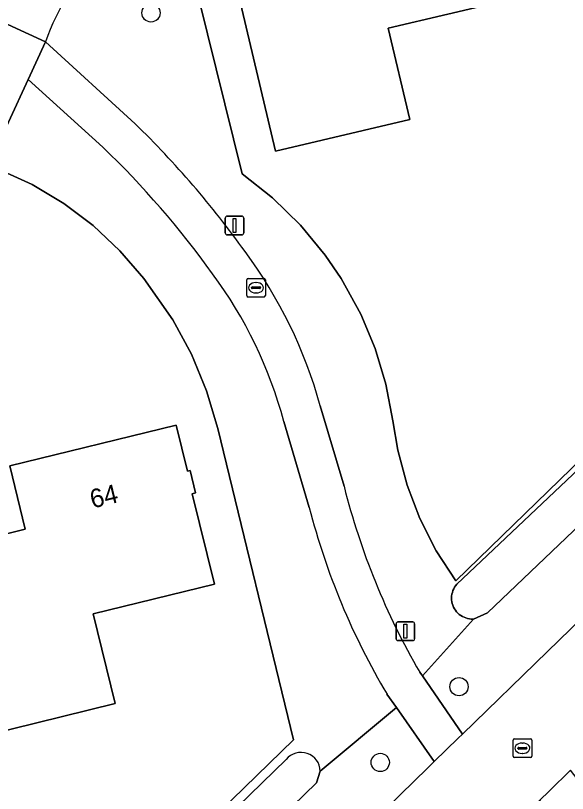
# Model space of a CAD drawing. Extents: x 157648 to 158502, y 379212 to 380938.
# Drawn here: x 158248.91 to 158278.51, y 380472.37 to 380514.11 of the extents above; entities that cross this region are included whole.
import ezdxf

# ---------------------------------------------------------------- set-up
doc = ezdxf.new("R2010")
doc.units = 0
for name, color, linetype in [('IMGEO_Berm_groen', 7, 'Continuous'), ('IMGEO_Boom', 7, 'Continuous'), ('IMGEO_Erf', 7, 'Continuous'), ('IMGEO_Groenvoorziening', 7, 'Continuous'), ('IMGEO_Lichtmast', 7, 'Continuous'), ('IMGEO_Pand', 7, 'Continuous'), ('IMGEO_Pand_nummerreeks', 7, 'Continuous'), ('IMGEO_Rijbaan_lokaal_gesloten', 7, 'Continuous'), ('IMGEO_Rioolput', 7, 'Continuous'), ('IMGEO_Voetpad_open', 7, 'Continuous'), ('IMGEO_Waterloop', 7, 'Continuous')]:
    doc.layers.add(name, color=color, linetype=linetype)

msp = doc.modelspace()

# ---------------------------------------------------------------- linework, layer by layer
at = {"layer": 'IMGEO_Berm_groen'}
msp.add_lwpolyline([(158250.925, 380454.131), (158271.031, 380473.749), (158271.369, 380474.079), (158269.334, 380476.98), (158265.254, 380473.57), (158265.055, 380472.934), (158206.97, 380416.487), (158206.469, 380416.402), (158201.9, 380412.048), (158203.076, 380407.926)], close=True, dxfattribs=at)
at = {"layer": 'IMGEO_Boom'}
for centre in [(158256.174, 380514.25), (158272.696, 380478.099), (158268.47, 380474.034)]:
    msp.add_circle(centre, 0.489, dxfattribs=at)
at = {"layer": 'IMGEO_Erf'}
for points in [[(158319.496, 380558.936), (158263.701, 380524.634), (158257.585, 380520.788), (158257.469, 380520.719), (158257.353, 380520.65), (158261.062, 380505.621), (158262.697, 380504.321), (158264.187, 380502.857), (158265.516, 380501.245), (158266.367, 380500), (158267.425, 380498.089), (158268.197, 380496.241), (158268.772, 380494.324), (158269.143, 380492.356), (158269.406, 380490.783), (158269.906, 380488.917), (158270.597, 380487.114), (158271.474, 380485.392), (158272.525, 380483.772), (158289.215, 380500), (158329.422, 380539.101), (158325.742, 380554.195), (158320.483, 380559.775)], [(158275.292, 380514.936), (158268.901, 380513.427), (158270.056, 380508.533), (158262.853, 380506.832), (158260.494, 380516.825)], [(158259.752, 380491.953), (158259.158, 380493.979), (158258.356, 380495.931), (158257.354, 380497.789), (158255.796, 380500), (158254.505, 380501.492), (158253.066, 380502.84), (158251.493, 380504.031), (158249.805, 380505.05), (158247.453, 380506.107), (158245.11, 380501.089), (158241.856, 380493.971)], [(158233.427, 380472.19), (158232.637, 380475.402), (158237.416, 380476.576), (158236.587, 380479.949), (158245.461, 380482.13), (158244.664, 380485.374), (158249.435, 380486.546), (158248.601, 380489.942), (158257.519, 380492.133), (158258.127, 380489.655), (158258.274, 380489.691), (158258.568, 380488.496), (158258.391, 380488.452), (158259.581, 380483.607), (158253.072, 380482.008), (158254.256, 380477.189), (158247.21, 380475.457), (158247.738, 380473.308), (158247.426, 380473.231), (158247.32, 380473.66), (158240.966, 380472.099)], [(158232.056, 380481.111), (158195.106, 380450.632), (158202.56, 380420.525), (158204.989, 380417.99), (158263.809, 380475.249), (158259.752, 380491.953)]]:
    msp.add_lwpolyline(points, dxfattribs=at)
at = {"layer": 'IMGEO_Groenvoorziening'}
for points in [[(158334.137, 380543.912), (158329.422, 380539.101), (158289.215, 380500), (158272.525, 380483.772), (158271.474, 380485.392), (158270.597, 380487.114), (158269.906, 380488.917), (158269.406, 380490.783), (158269.143, 380492.356), (158268.772, 380494.324), (158268.197, 380496.241), (158267.425, 380498.089), (158266.367, 380500), (158265.516, 380501.245), (158264.187, 380502.857), (158262.697, 380504.321), (158261.062, 380505.621), (158257.353, 380520.65)], [(158250.517, 380512.693), (158255.325, 380508.305)], [(158253.591, 380507.049), (158249.589, 380510.681), (158247.453, 380506.107), (158249.805, 380505.05), (158251.493, 380504.031), (158253.066, 380502.84), (158254.505, 380501.492), (158255.796, 380500), (158257.354, 380497.789), (158258.356, 380495.931), (158259.158, 380493.979), (158259.752, 380491.953), (158263.809, 380475.249), (158204.989, 380417.99), (158205.522, 380417.551)], [(158270.591, 380478.878), (158270.73, 380478.676), (158273.465, 380481.728), (158273.452, 380481.728), (158273.351, 380481.729), (158273.251, 380481.739), (158273.153, 380481.759), (158273.056, 380481.787), (158272.963, 380481.823), (158272.873, 380481.868), (158272.788, 380481.92), (158272.707, 380481.98), (158272.632, 380482.047), (158272.564, 380482.121), (158272.502, 380482.2), (158272.448, 380482.284), (158272.401, 380482.373), (158272.363, 380482.466), (158272.332, 380482.562), (158272.311, 380482.66), (158272.299, 380482.76), (158272.295, 380482.86), (158272.3, 380482.96), (158272.315, 380483.06), (158272.338, 380483.157), (158272.37, 380483.252), (158272.41, 380483.344), (158272.458, 380483.433), (158272.514, 380483.516), (158272.577, 380483.594), (158289.923, 380500)], [(158265.256, 380493.17), (158266.53, 380488.852)], [(158264.661, 380487.712), (158263.298, 380492.332)], [(158265.254, 380473.57), (158269.334, 380476.98), (158268.832, 380477.696)], [(158205.787, 380418.134), (158263.422, 380474.193)]]:
    msp.add_lwpolyline(points, dxfattribs=at)
msp.add_lwpolyline([(158332.358, 380537.527), (158293.02, 380500), (158274.224, 380482.069), (158273.465, 380481.728), (158270.73, 380478.676), (158272.883, 380475.555), (158277.441, 380479.984), (158298.039, 380500), (158339.285, 380540.082), (158336.691, 380542), (158332.462, 380538.012)], close=True, dxfattribs=at)
for centre, radius, start, end in [((158263.377, 380508.142), 13.641, 136.3346, 160.5134), ((158219.142, 380471.243), 51.796, 35.6688, 45.6876), ((158219.256, 380471.391), 49.501, 35.6629, 46.083), ((158240.763, 380486.348), 25.425, 15.5636, 36.4254), ((158240.611, 380486.26), 23.485, 14.9846, 36.5662), ((158303.644, 380498.15), 38.261, 194.064, 210.2442), ((158301.93, 380497.356), 38.496, 194.5074, 210.7096), ((158264.223, 380473.542), 1.032, 1.5405, 140.8968)]:
    msp.add_arc(centre, radius, start, end, dxfattribs=at)
at = {"layer": 'IMGEO_Lichtmast'}
for p, q in [((158260.159, 380502.443), (158260.159, 380503.243)), ((158260.159, 380503.243), (158260.159, 380502.443)), ((158260.259, 380503.343), (158261.049, 380503.343)), ((158261.049, 380503.343), (158260.259, 380503.343)), ((158261.149, 380503.243), (158261.149, 380502.443)), ((158261.149, 380502.443), (158261.149, 380503.243)), ((158261.049, 380502.343), (158260.259, 380502.343)), ((158260.259, 380502.343), (158261.049, 380502.343)), ((158269.322, 380480.671), (158269.322, 380481.471)), ((158269.322, 380481.471), (158269.322, 380480.671)), ((158269.422, 380481.571), (158270.212, 380481.571)), ((158270.212, 380481.571), (158269.422, 380481.571)), ((158270.312, 380481.471), (158270.312, 380480.671)), ((158270.312, 380480.671), (158270.312, 380481.471)), ((158270.212, 380480.571), (158269.422, 380480.571)), ((158269.422, 380480.571), (158270.212, 380480.571))]:
    msp.add_line(p, q, dxfattribs=at)
for points in [[(158260.579, 380503.218), (158260.729, 380503.218), (158260.729, 380502.468), (158260.579, 380502.468), (158260.579, 380503.218)], [(158269.742, 380481.446), (158269.892, 380481.446), (158269.892, 380480.696), (158269.742, 380480.696), (158269.742, 380481.446)]]:
    msp.add_lwpolyline(points, dxfattribs=at)
for centre, start, end in [((158260.259, 380503.243), 90, 180), ((158260.259, 380503.243), 90, 180), ((158261.049, 380503.243), 0, 90), ((158261.049, 380503.243), 360, 90), ((158260.259, 380502.443), 180, 270), ((158260.259, 380502.443), 180, 270), ((158261.049, 380502.443), 270, 0), ((158261.049, 380502.443), 270, 0), ((158269.422, 380481.471), 90, 180), ((158269.422, 380481.471), 90, 180), ((158270.212, 380481.471), 0, 90), ((158270.212, 380481.471), 360, 90), ((158269.422, 380480.671), 180, 270), ((158269.422, 380480.671), 180, 270), ((158270.212, 380480.671), 270, 0), ((158270.212, 380480.671), 270, 0)]:
    msp.add_arc(centre, 0.1, start, end, dxfattribs=at)
at = {"layer": 'IMGEO_Pand'}
for points in [[(158273.263, 380523.53), (158264.531, 380521.468), (158265.356, 380517.973), (158260.494, 380516.825), (158262.853, 380506.832), (158270.056, 380508.533), (158268.901, 380513.427), (158275.292, 380514.936)], [(158258.391, 380488.452), (158258.568, 380488.496), (158258.274, 380489.691), (158258.127, 380489.655), (158257.519, 380492.133), (158248.601, 380489.942), (158249.435, 380486.546), (158244.664, 380485.374), (158245.461, 380482.13), (158247.21, 380475.457), (158254.256, 380477.189), (158253.072, 380482.008), (158259.581, 380483.607)]]:
    msp.add_lwpolyline(points, close=True, dxfattribs=at)
at = {"layer": 'IMGEO_Rijbaan_lokaal_gesloten'}
msp.add_lwpolyline([(158298.039, 380500), (158277.441, 380479.984), (158272.883, 380475.555), (158272.656, 380475.334), (158271.369, 380474.079), (158271.031, 380473.749), (158250.925, 380454.131), (158203.076, 380407.926), (158202.965, 380407.819), (158201.329, 380406.238), (158201.205, 380406.119), (158169.223, 380374.76), (158172.867, 380370.956), (158173.119, 380370.694), (158174.013, 380371.614), (158174.854, 380372.479), (158183.798, 380381.68), (158203.283, 380400.795), (158204.847, 380402.186), (158204.985, 380402.319), (158277.006, 380471.994), (158277.54, 380472.51), (158278.68, 380473.614)], dxfattribs=at)
at = {"layer": 'IMGEO_Rioolput'}
for p, q in [((158261.31, 380499.079), (158261.31, 380499.931)), ((158261.385, 380500.005), (158262.237, 380500.005)), ((158261.798, 380499.785), (158261.823, 380499.785)), ((158262.311, 380499.931), (158262.311, 380499.079)), ((158261.569, 380499.499), (158261.569, 380499.511)), ((158262.007, 380499.462), (158261.609, 380499.462)), ((158261.612, 380499.548), (158262.01, 380499.548)), ((158261.821, 380499.225), (158261.796, 380499.225)), ((158262.053, 380499.511), (158262.053, 380499.499)), ((158262.237, 380499.005), (158261.385, 380499.005)), ((158275.595, 380474.371), (158275.595, 380475.223)), ((158275.67, 380475.297), (158276.522, 380475.297)), ((158276.083, 380475.077), (158276.108, 380475.077)), ((158276.596, 380475.223), (158276.596, 380474.371)), ((158275.854, 380474.791), (158275.854, 380474.803)), ((158276.292, 380474.754), (158275.894, 380474.754)), ((158275.897, 380474.84), (158276.295, 380474.84)), ((158276.338, 380474.803), (158276.338, 380474.791)), ((158276.522, 380474.297), (158275.67, 380474.297)), ((158276.106, 380474.517), (158276.081, 380474.517))]:
    msp.add_line(p, q, dxfattribs=at)
for points in [[(158261.31, 380499.079), (158261.31, 380499.931)], [(158261.385, 380500.005), (158262.237, 380500.005)], [(158262.311, 380499.931), (158262.311, 380499.079)], [(158262.237, 380499.005), (158261.385, 380499.005)], [(158275.595, 380474.371), (158275.595, 380475.223)], [(158275.67, 380475.297), (158276.522, 380475.297)], [(158276.596, 380475.223), (158276.596, 380474.371)], [(158276.522, 380474.297), (158275.67, 380474.297)]]:
    msp.add_lwpolyline(points, dxfattribs=at)
for centre, radius, start, end in [((158261.387, 380499.929), 0.0765, 91.552, 178.448), ((158261.387, 380499.929), 0.0765, 91.552, 178.448), ((158262.235, 380499.929), 0.0765, 1.552, 88.448), ((158262.235, 380499.929), 0.0765, 1.552, 88.448), ((158261.609, 380499.508), 0.0403, 85.8775, 175.7526), ((158261.606, 380499.498), 0.0366, 178.938, 274.7102), ((158262.01, 380499.505), 0.043, 264.8664, 352.4533), ((158262.014, 380499.51), 0.0386, 1.7309, 96.639), ((158261.387, 380499.081), 0.0765, 181.552, 268.448), ((158261.387, 380499.081), 0.0765, 181.552, 268.448), ((158262.235, 380499.081), 0.0765, 271.552, 358.448), ((158262.235, 380499.081), 0.0765, 271.552, 358.448), ((158275.672, 380475.221), 0.0765, 91.552, 178.448), ((158275.672, 380475.221), 0.0765, 91.552, 178.448), ((158276.52, 380475.221), 0.0765, 1.552, 88.448), ((158276.52, 380475.221), 0.0765, 1.552, 88.448), ((158275.894, 380474.8), 0.0403, 85.8775, 175.7526), ((158275.891, 380474.79), 0.0366, 178.938, 274.7102), ((158276.295, 380474.797), 0.043, 264.8664, 352.4533), ((158276.299, 380474.802), 0.0386, 1.7309, 96.639), ((158275.672, 380474.373), 0.0765, 181.552, 268.448), ((158275.672, 380474.373), 0.0765, 181.552, 268.448), ((158276.52, 380474.373), 0.0765, 271.552, 358.448), ((158276.52, 380474.373), 0.0765, 271.552, 358.448)]:
    msp.add_arc(centre, radius, start, end, dxfattribs=at)
for centre, major_axis, ratio, start_param, end_param in [((158261.797, 380499.505), (-0.387, 0.002), 0.722429, 4.712389, 7.853982), ((158261.822, 380499.505), (-0.39, 0.002), 0.717154, 1.570796, 4.712389), ((158276.082, 380474.797), (-0.387, 0.002), 0.722429, 4.712389, 7.853982), ((158276.107, 380474.797), (-0.39, 0.002), 0.717154, 1.570796, 4.712389)]:
    msp.add_ellipse(centre, major_axis=major_axis, ratio=ratio, start_param=start_param, end_param=end_param, dxfattribs=at)
at = {"layer": 'IMGEO_Voetpad_open'}
for points in [[(158248.235, 380515.431), (158247.594, 380514.038), (158250.517, 380512.693)], [(158241.856, 380493.971), (158245.11, 380501.089), (158247.453, 380506.107), (158249.589, 380510.681), (158250.517, 380512.693), (158247.594, 380514.038), (158242.804, 380503.631), (158240.314, 380498.123), (158239.292, 380495.89)], [(158255.325, 380508.305), (158250.517, 380512.693), (158249.589, 380510.681), (158253.591, 380507.049)], [(158266.53, 380488.852), (158265.256, 380493.17)], [(158263.298, 380492.332), (158264.661, 380487.712)], [(158268.832, 380477.696), (158269.334, 380476.98), (158271.369, 380474.079), (158272.656, 380475.334), (158272.883, 380475.555), (158270.73, 380478.676), (158270.591, 380478.878)], [(158280.589, 380471.146), (158280.476, 380471.294), (158280.362, 380471.441), (158278.68, 380473.614), (158277.54, 380472.51), (158277.006, 380471.994), (158278.537, 380470.006), (158278.775, 380469.698), (158279.013, 380469.39)]]:
    msp.add_lwpolyline(points, dxfattribs=at)
for centre, radius, start, end in [((158263.377, 380508.142), 13.641, 136.3346, 160.5134), ((158219.142, 380471.243), 51.796, 35.6688, 45.6876), ((158219.256, 380471.391), 49.501, 35.6629, 46.083), ((158240.763, 380486.348), 25.425, 15.5636, 36.4254), ((158240.611, 380486.26), 23.485, 14.9846, 36.5662), ((158303.644, 380498.15), 38.261, 194.064, 210.2442), ((158301.93, 380497.356), 38.496, 194.5074, 210.7096)]:
    msp.add_arc(centre, radius, start, end, dxfattribs=at)
at = {"layer": 'IMGEO_Waterloop'}
for points in [[(158289.923, 380500), (158272.577, 380483.594), (158272.514, 380483.516), (158272.458, 380483.433), (158272.41, 380483.344), (158272.37, 380483.252), (158272.338, 380483.157), (158272.315, 380483.06), (158272.3, 380482.96), (158272.295, 380482.86), (158272.299, 380482.76), (158272.311, 380482.66), (158272.332, 380482.562), (158272.363, 380482.466), (158272.401, 380482.373), (158272.448, 380482.284), (158272.502, 380482.2), (158272.564, 380482.121), (158272.632, 380482.047), (158272.707, 380481.98), (158272.788, 380481.92), (158272.873, 380481.868), (158272.963, 380481.823), (158273.056, 380481.787), (158273.153, 380481.759), (158273.251, 380481.739), (158273.351, 380481.729), (158273.452, 380481.728), (158273.465, 380481.728), (158274.224, 380482.069), (158293.02, 380500)], [(158263.422, 380474.193), (158205.787, 380418.134)], [(158206.469, 380416.402), (158206.97, 380416.487), (158265.055, 380472.934), (158265.254, 380473.57)]]:
    msp.add_lwpolyline(points, dxfattribs=at)
msp.add_arc((158264.223, 380473.542), 1.032, 1.5405, 140.8968, dxfattribs=at)

# ---------------------------------------------------------------- texts
at = {"layer": 'IMGEO_Pand_nummerreeks'}
msp.add_text('64', height=1, rotation=13.8026, dxfattribs=at).set_placement((158253.04, 380487.655))

doc.saveas('drawing.dxf')
